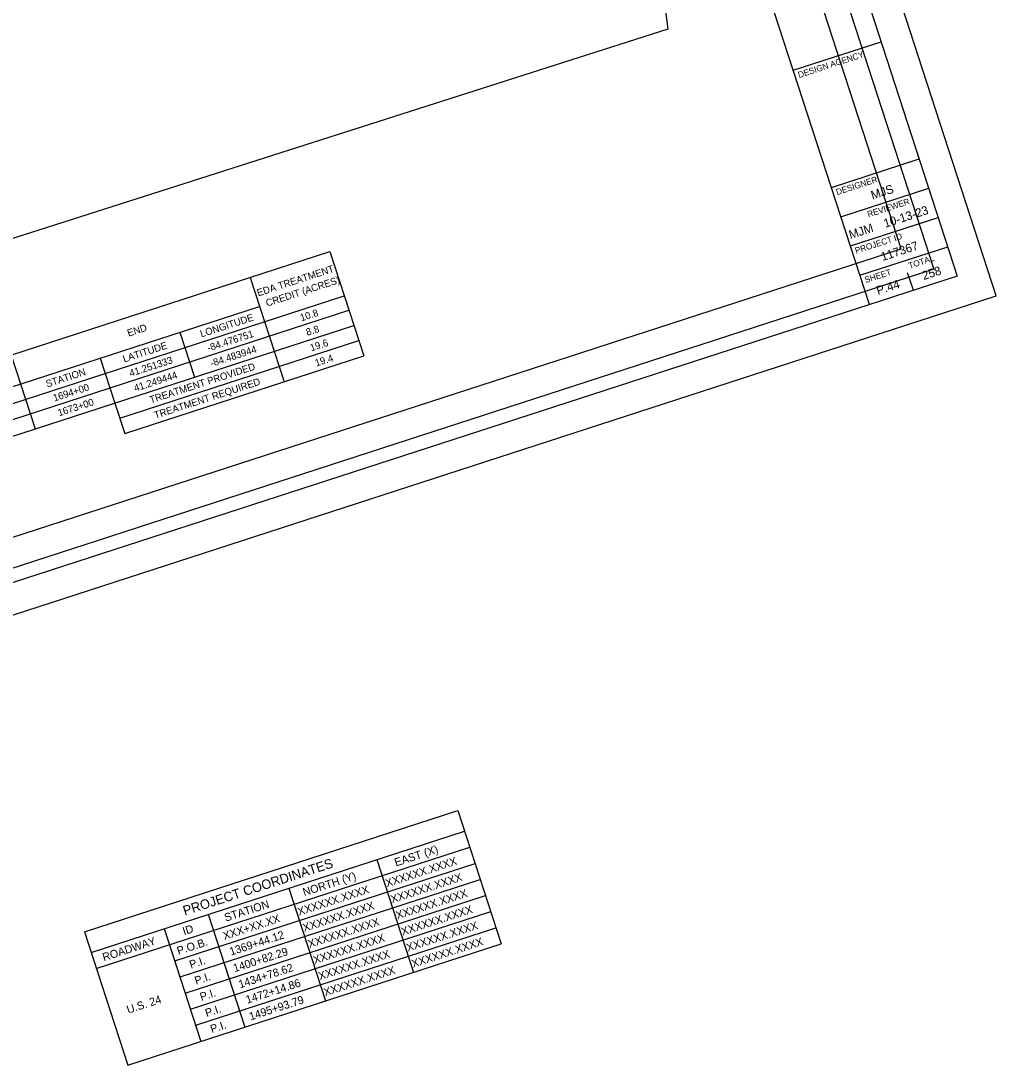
# Model space of a CAD drawing. Extents: x -468563856 to 36492962, y -306094093 to 11899197.
# Drawn here: x 1824382 to 1829131, y 526302 to 531389 of the extents above; entities that cross this region are included whole.
import ezdxf

# ---------------------------------------------------------------- set-up
doc = ezdxf.new("R2010")
doc.units = 0
for name, color, linetype in [('Default', 7, 'Continuous'), ('Level 40', 7, 'Continuous'), ('Level 63', 7, 'Continuous'), ('SC_Scratch1', 7, 'Continuous'), ('SH_Border', 7, 'Continuous'), ('SH_Cut_Line', 7, 'Continuous'), ('SH_Data', 7, 'Continuous')]:
    doc.layers.add(name, color=color, linetype=linetype)

msp = doc.modelspace()

# ---------------------------------------------------------------- linework, layer by layer
at = {"layer": 'Default'}
for p, q in [((1821719.1, 528911.4), (1825886.6, 530264.4)), ((1825886.6, 530264.4), (1826051.4, 529756.7)), ((1825498.7, 530138.5), (1825663.6, 529630.8)), ((1821788.9, 528696.4), (1825956.4, 530049.4)), ((1823217.5, 529242), (1825544.5, 529997.5)), ((1821811.8, 528625.8), (1825979.3, 529978.8)), ((1821835.8, 528551.8), (1826003.3, 529904.8)), ((1824863.8, 529453), (1826027.3, 529830.8)), ((1825156.7, 529871.6), (1825180.7, 529797.5)), ((1825180.7, 529797.5), (1825227.6, 529653)), ((1824335.2, 529760.8), (1824452, 529401.1)), ((1824768.8, 529745.7), (1824792.9, 529671.6)), ((1824887.9, 529379), (1826051.4, 529756.7)), ((1824792.9, 529671.6), (1824839.8, 529527.1)), ((1824839.8, 529527.1), (1824887.9, 529379))]:
    msp.add_line(p, q, dxfattribs=at)
at = {"layer": 'Level 40'}
for p, q in [((1824691.5, 526951), (1826510.6, 527541.5)), ((1826510.6, 527541.5), (1826721.3, 526892.4)), ((1824723.9, 526851.1), (1826543, 527441.7)), ((1824749.4, 526772.6), (1826568.4, 527363.2)), ((1826115, 527302.7), (1826293.3, 526753.4)), ((1825131.6, 526810), (1826593.9, 527284.7)), ((1825157, 526731.5), (1826619.4, 527206.3)), ((1825687, 527163.7), (1825865.3, 526614.5)), ((1825182.5, 526653), (1826644.9, 527127.8)), ((1825208, 526574.5), (1826670.4, 527049.3)), ((1825294.6, 527036.4), (1825472.9, 526487.1)), ((1824691.5, 526951), (1824902.3, 526301.8)), ((1825080.6, 526966.9), (1825258.9, 526417.6)), ((1825233.5, 526496.1), (1826695.8, 526970.8)), ((1824902.3, 526301.8), (1826721.3, 526892.4))]:
    msp.add_line(p, q, dxfattribs=at)
at = {"layer": 'Level 63'}
for points in [[(1817088.6, 533305.9), (1826789.4, 536455.4), (1828827.2, 530178.6), (1819126.4, 527029.2)], [(1819195.4, 527203), (1828668.6, 530278.5), (1826708.4, 536316.3), (1817235.1, 533240.7)]]:
    msp.add_lwpolyline(points, close=True, dxfattribs=at)
at = {"layer": 'SC_Scratch1'}
msp.add_lwpolyline([(1818754.7, 531265.4), (1818680.3, 532626), (1826365, 535120.9), (1826839.3, 533890.3), (1827446.9, 532018.9), (1827532.1, 531348.3), (1819682.5, 528840.1), (1819362.2, 529394.3)], close=True, dxfattribs=at)
at = {"layer": 'SH_Border'}
for p, q in [((1828514.3, 530006.7), (1826568.9, 535998.8)), ((1828143.7, 531148), (1828571.7, 531287)), ((1828329, 530577.3), (1828757, 530716.3)), ((1828375.3, 530434.7), (1828803.3, 530573.6)), ((1828421.6, 530292), (1828849.6, 530431)), ((1828468, 530149.3), (1828896, 530288.3))]:
    msp.add_line(p, q, dxfattribs=at)
msp.add_lwpolyline([(1817866.1, 533173.3), (1826996.9, 536137.7), (1828942.3, 530145.6), (1819811.4, 527181.2)], close=True, dxfattribs=at)
at = {"layer": 'SH_Cut_Line'}
msp.add_lwpolyline([(1819429.8, 526899.6), (1829131.3, 530049.3), (1827093.3, 536326.7), (1817391.7, 533177)], close=True, dxfattribs=at)
at = {"layer": 'SH_Data'}
for p, q in [((1828450.4, 530932.2), (1828450.4, 530932.2)), ((1828728.3, 530076.1), (1828700.5, 530161.7)), ((1828605.1, 530091.3), (1828605.1, 530091.3))]:
    msp.add_line(p, q, dxfattribs=at)

# ---------------------------------------------------------------- texts
at = {"layer": 'Default'}
for s, p in [('EDA TREATMENT ', (1825538, 530046.1)), ('CREDIT (ACRES)', (1825581.1, 529996.3)), ('10.8', (1825748, 529924.5)), ('LONGITUDE', (1825261.4, 529846.4)), ('END', (1824906.5, 529850.1)), ('8.8', (1825777.1, 529854.1)), ('-84.476751', (1825295.8, 529777.7)), ('19.6', (1825796.3, 529778.5)), ('LATITUDE', (1824885.1, 529724.3)), ('-84.483944', (1825310.7, 529702.6)), ('41.251333', (1824916.3, 529654.5)), ('19.4', (1825820.4, 529704.4)), ('STATION', (1824509.9, 529602.5)), ('41.249444', (1824938.9, 529581.9)), ('TREATMENT PROVIDED', (1825014.7, 529524.7)), ('TREATMENT REQUIRED', (1825037.1, 529450.1)), ('1694+00', (1824545.1, 529534)), ('1673+00', (1824567.9, 529461.5))]:
    msp.add_text(s, height=34.66, rotation=17.9864, dxfattribs=at).set_placement(p)
at = {"layer": 'Level 40'}
for s, height, p in [('EAST (X)', 39, (1826208.6, 527269.2)), ('PROJECT COORDINATES', 46.5, (1825180.4, 527030)), ('XXXXXX.XXXX', 39, (1826164.7, 527168.2)), ('NORTH (Y)', 39, (1825762.1, 527124.3)), ('XXXXXX.XXXX', 39, (1826190.1, 527089.8)), ('XXXXXX.XXXX', 39, (1825736.7, 527029.3)), ('XXXXXX.XXXX', 39, (1826215.6, 527011.3)), ('STATION', 39, (1825380.2, 527000.3)), ('XXXXXX.XXXX', 39, (1825762.1, 526950.8)), ('XXX+XX.XX', 39, (1825373.4, 526911.3)), ('XXXXXX.XXXX', 39, (1826241.1, 526932.8)), ('ID', 39, (1825176.9, 526934.3)), ('XXXXXX.XXXX', 39, (1825787.6, 526872.3)), ('XXXXXX.XXXX', 39, (1826266.6, 526854.3)), ('1369+44.12', 39, (1825405, 526834.8)), ('XXXXXX.XXXX', 39, (1825813.1, 526793.9)), ('ROADWAY', 39, (1824786.4, 526807.5)), ('P.O.B.', 39, (1825149.3, 526838.6)), ('XXXXXX.XXXX', 39, (1826292, 526775.9)), ('1400+82.29', 39, (1825423.1, 526754)), ('XXXXXX.XXXX', 39, (1825838.6, 526715.4)), ('P.I.', 39, (1825210, 526771.5)), ('1434+78.62', 39, (1825448.9, 526675.6)), ('XXXXXX.XXXX', 39, (1825864, 526636.9)), ('P.I.', 39, (1825235.5, 526693.1)), ('1472+14.86', 39, (1825484.7, 526600.5)), ('U.S. 24', 39, (1824904.6, 526552.2)), ('P.I.', 39, (1825261, 526614.6)), ('1495+93.79', 39, (1825500.6, 526518.9)), ('P.I.', 39, (1825286.4, 526536.1)), ('P.I.', 39, (1825311.9, 526457.7))]:
    msp.add_text(s, height=height, rotation=17.9864, dxfattribs=at).set_placement(p)
at = {"layer": 'SH_Data'}
for s, height, p in [('DESIGN AGENCY', 30, (1828171.9, 531109.8)), ('DESIGNER', 30, (1828357.2, 530539.2)), ('MJS', 42, (1828529.3, 530517.8)), ('REVIEWER', 30, (1828509.6, 530430.9)), ('10-13-23', 42, (1828591.4, 530380.2)), ('MJM', 42, (1828422, 530325.2)), ('PROJECT ID', 30, (1828449.8, 530253.8)), ('117367', 42, (1828578, 530218.2)), ('TOTAL', 30, (1828710.1, 530180.6)), ('258', 42, (1828779, 530125.7)), ('SHEET', 30, (1828496.1, 530111.2)), ('P.44', 42, (1828556.4, 530053.4))]:
    msp.add_text(s, height=height, rotation=17.9864, dxfattribs=at).set_placement(p)

doc.saveas('drawing.dxf')
